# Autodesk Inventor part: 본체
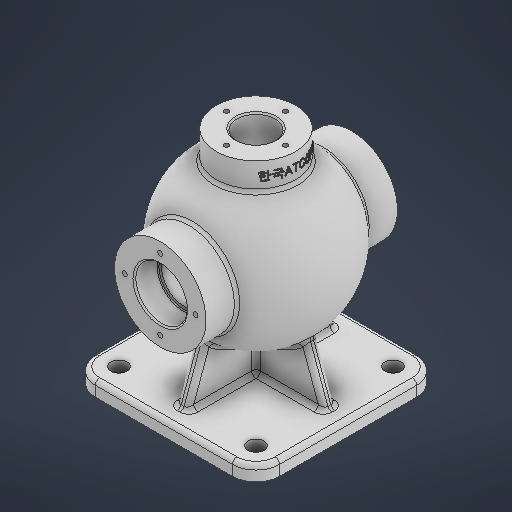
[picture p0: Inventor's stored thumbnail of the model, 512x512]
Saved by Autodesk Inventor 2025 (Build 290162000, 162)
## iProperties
Created: 2025-08
Part Number: 본체
Material: 일반
Document SubType Name: Modeling
Designer: infra002
Density: 1 g/cm^3
Appearance: 기본값
Author: infra002
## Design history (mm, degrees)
sketch "스케치1"
  geometry: L1 (46.5, 62.5)-(-46.5, 62.5); L2 (-62.5, 46.5)-(-62.5, -46.5); L3 (-46.5, -62.5)-(46.5, -62.5); L4 (62.5, -46.5)-(62.5, 46.5); L5 (62.5, 62.5)-(-62.5, -62.5); L6 (-62.5, 62.5)-(62.5, -62.5); A1 r 16 centre (46.5, -46.5) between (46.5, -62.5) and (62.5, -46.5); A2 r 16 centre (46.5, 46.5) between (62.5, 46.5) and (46.5, 62.5); A3 r 16 centre (-46.5, 46.5) between (-46.5, 62.5) and (-62.5, 46.5); A4 r 16 centre (-46.5, -46.5) between (-62.5, -46.5) and (-46.5, -62.5); 1 further point
  constraints: 12 end point, 8 point on circle, 8 point on line, 8 tangent, 4 centre point, 3 equal radius, 2 midpoint, 2 parallel, 1 horizontal, 1 perpendicular
  dimensions: "d0" = 125 distance of L6.end L5.end; "d1" = 125 distance of L5.end L6.start; "d2" = 16 radius of A1
extrude "돌출1" new body sketch "스케치1" distance "d3" = 10; taper "d4" = 0 deg
node "작업 평면1"
sketch "스케치2"
  geometry: L1 (0, 54)-(0, -54); C1 r 44 at (0, 0); A1 r 54 centre (0, 0) between (0, 54) and (0, -54); 3 further points
  constraints: 2 centre point, 2 coincident, 2 end point, 2 point on circle, 1 vertical, 1 vertical alignment
  dimensions: "d6" = 108 diameter of A1; "d7" = 88 diameter of C1
revolve "회전1" sketch "스케치2" stored, may be unused: angle "d8" = 90 deg
sketch "스케치3"
  geometry: L1 (10, 46.5)-(10, -46.5) reference; L2 (10, -50.5)-(50, -35.941); L3 (10, 50.5)-(50, 35.941); L4 (0, 62.5)-(0, 46.5) reference; L5 (0, 46.5)-(0, 62.5) reference; L6 (0, -46.5)-(0, 46.5) reference; L7 (0, -62.5)-(0, -46.5) reference; L8 (0, -46.5)-(0, -62.5) reference; L9 (0, 46.5)-(0, -46.5) reference; L10 (10, 62.5)-(10, 46.5) reference; L11 (10, 46.5)-(10, -46.5) reference; L12 (10, -46.5)-(10, -62.5) reference; L13 (10, -62.5)-(10, -46.5) reference; L14 (10, -46.5)-(10, 46.5) reference; L15 (10, 46.5)-(10, 62.5) reference; L16 (50, 35.941)-(50, -35.941); C1 r 54 at (85, 0) reference; 7 further points
  constraints: 6 end point, 2 point on line, 1 vertical, 1 vertical alignment
  dimensions: "d9" = 12 distance of point (10, -62.5) L2.start; "d10" = 70 deg angle of L1 L2; "d11" = 12 distance of point (10, 62.5) L3.start; "d12" = 70 deg angle of L1 L3 (= d10); "d81" = 40 distance between parallel lines of L1 L16
extrude "돌출2" join sketch "스케치3" stored distance "d13" = 8; taper "d14" = 0 deg
sketch "스케치4"
  geometry: L1 (62.5, 10)-(46.5, 10) reference; L2 (50.5, 10)-(35.941, 50); L3 (-46.5, 10)-(46.5, 10) reference; L4 (-50.5, 10)-(-35.941, 50); L5 (-4, 46.186)-(-4, 46.186) reference; L6 (4, 46.186)-(4, 46.186) reference; L7 (-4, 10)-(4, 10) reference; L8 (4, 10)-(-4, 10) reference; L9 (46.5, 10)-(62.5, 10) reference; L10 (62.5, 10)-(46.5, 10) reference; L11 (46.5, 10)-(-46.5, 10) reference; L12 (-46.5, 10)-(-62.5, 10) reference; L13 (-62.5, 10)-(-46.5, 10) reference; L14 (-46.5, 10)-(46.5, 10) reference; L15 (-35.941, 50)-(35.941, 50); A1 r 54 centre (0, 85) between (4, 31.148) and (-4, 31.148) reference; 7 further points; 2 other entities
  constraints: 6 end point, 2 point on line, 1 horizontal, 2 other
  dimensions: "d16" = 70 deg angle of L3 L4; "d17" = 70 deg angle of L3 L2; "d18" = 12 distance of point (-62.5, 10) L4.start; "d19" = 12 distance of L1.start L2.start (= d18); "d82" = 40 distance between parallel lines of L3 L15
extrude "돌출3" join sketch "스케치4" stored distance "d20" = 8; taper "d21" = 0 deg
sketch "스케치5"
  geometry: L1 (85, -44)-(85, 44); A1 r 44 centre (85, 0) between (50, -26.665) and (50, 26.665) reference; A2 r 44 centre (85, 0) between (85, -44) and (85, 44); 3 further points
  constraints: 2 end point, 2 point on circle, 1 centre point, 1 coincident, 1 vertical, 1 vertical alignment
  dimensions: "d22" = 88 diameter of A2
revolve "회전2" sketch "스케치5" stored, may be unused: angle "d23" = 90 deg
node "작업 평면2"
sketch "스케치6"
  geometry: C1 r 27 at (0, 0); 1 further point
  constraints: 1 centre point, 1 coincident
  dimensions: "d25" = 54 diameter of C1
extrude "돌출4" join sketch "스케치6" stored distance "d26" = 8; taper "d27" = 0 deg
node "작업 평면3"
sketch "스케치7"
  geometry: C1 r 31 at (0, 85); A1 r 54 centre (0, 85) between (37.385, 46.034) and (-37.385, 46.034) reference; 1 further point
  constraints: 1 centre point, 1 coincident
  dimensions: "d29" = 62 diameter of C1
extrude "돌출5" join sketch "스케치7" stored distance "d30" = 10; taper "d31" = 0 deg
sketch "스케치8"
  geometry: C1 r 31 at (0, 0) reference; 1 further point
hole "구멍1" sketch "스케치8" at (0, 0) diameter "d32" = 30; stored, may be unused: countersink angle "d36" = 90 deg, drill point angle "d38" = 118 deg; dims "d33" = 12, "d34" = 35, "d35" = 16, "d37" = 8
sketch "스케치9" dims "d39" = 48
  geometry: L1 (0, 0)-(0, 40.263); C1 r 17.5 at (0, 0) reference; C2 r 31 at (0, 0) reference; 5 further points
  constraints: 2 end point, 1 coincident, 1 point on line, 1 vertical, 1 vertical alignment, 7 other
  dimensions: "d42" = 360 deg dimension on C1.centre point (0, 24) (derived)
hole "구멍2" sketch "스케치9" at (0, 24), (-24, 0), (0, -24), (24, 0) diameter "d44" = 3.242; stored, may be unused: countersink angle "d48" = 90 deg, drill point angle "d50" = 118 deg; dims "d45" = 12, "d46" = 35, "d47" = 16, "d49" = 15
fillet "모깎기1" dims "d51" = 0.6
sketch "스케치10"
  geometry: 1 further point
hole "구멍3" sketch "스케치10" at (0, 0) diameter "d52" = 26; stored, may be unused: countersink angle "d56" = 90 deg, drill point angle "d58" = 118 deg; dims "d53" = 8, "d54" = 4, "d55" = 2, "d57" = 65.25
sketch "스케치11" dims "d12" = 70 deg (= d10), "d59" = 40
  geometry: L1 (0, 0)-(-34.3, 0); 5 further points
  constraints: 2 end point, 1 coincident, 1 horizontal, 1 horizontal alignment, 1 point on line, 7 other
  dimensions: "d62" = 360 deg dimension on point (0, 0) point (-20, 0) (derived)
hole "구멍4" sketch "스케치11" at (-20, 0), (0, -20), (20, 0), (0, 20) diameter "d64" = 3.242; stored, may be unused: countersink angle "d68" = 90 deg, drill point angle "d70" = 118 deg; dims "d12" = 70 deg (= d10), "d65" = 9, "d66" = 4, "d67" = 2, "d69" = 11
sketch "스케치12"
  geometry: L1 (46.5, -46.5)-(-46.5, -46.5); L2 (-46.5, -46.5)-(-46.5, 46.5); L3 (-46.5, 46.5)-(46.5, 46.5); L4 (46.5, 46.5)-(46.5, -46.5); L5 (46.5, -46.5)-(-46.5, 46.5); L6 (-46.5, -46.5)-(46.5, 46.5); 1 further point
  constraints: 12 end point, 2 midpoint, 2 parallel, 1 horizontal, 1 perpendicular
  dimensions: "d71" = 93 distance of L2.end L3.end; "d72" = 93 distance of L1.end L2.end
hole "구멍5" sketch "스케치12" at (-46.5, -46.5), (-46.5, 46.5), (46.5, 46.5), (46.5, -46.5) diameter "d73" = 11; stored, may be unused: countersink angle "d77" = 90 deg, drill point angle "d79" = 118 deg; dims "d74" = 9, "d75" = 4, "d76" = 2, "d78" = 11
fillet "모깎기3" dims "d83" = 3
fillet "모깎기4" dims "d84" = 3
node "작업 평면4"
sketch "스케치13" dims "d0" = 125, "d1" = 125, "d2" = 16
  geometry: L1 (153.427, 8.724)-(153.427, -8.724); L2 (153.427, -8.724)-(128.573, -8.724); L3 (128.573, -8.724)-(128.573, 8.724); L4 (128.573, 8.724)-(153.427, 8.724); L5 (150, -27)-(150, 27) reference; L6 (0, 46.5)-(0, -46.5) reference; 4 further points
  constraints: 3 midpoint, 1 horizontal alignment, 2 other
  dimensions: "d86" = 9 distance from line of L5 point (141, 8.724)
feature "엠보싱1" sketch "스케치13" dims "d0" = 125, "d1" = 125, "d2" = 16, "d87" = 0.5, "d88" = 0
chamfer "모따기1" distance "d89" = 1; stored, may be unused: second distance "d90" = 2, angle "d91" = 45 deg
node "솔리드1"
mirror "미러1"
node "투영된 루프1"
node "투영된 루프2"
node "투영된 루프3"
node "투영된 루프4"
node "투영된 루프5"
node "투영된 루프6"
node "스케치 - 원형 패턴1" dims "d42" = 360 deg (derived)
node "스케치 - 원형 패턴2" dims "d12" = 70 deg (= d10), "d62" = 360 deg (derived)
feature "A9D066F2-1C7D-4E18-AEED-F7BC21143FA4" dims "d52" = 26, "d53" = 8, "d54" = 4, "d55" = 2, "d56" = 90 deg, "d57" = 65.25, "d58" = 118 deg
other parameters: "d5" = 85, "d28" = 65, "d85" = 27
